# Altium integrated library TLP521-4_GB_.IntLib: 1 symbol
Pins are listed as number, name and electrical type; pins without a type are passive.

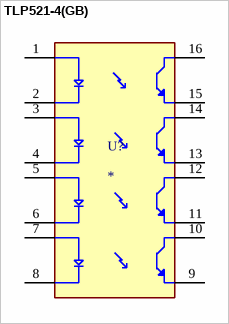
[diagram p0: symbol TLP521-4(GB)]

## TLP521-4(GB)
designator U?
Optocoupler, Quad, Transistor o/p; MF: Toshiba; MP: TLP521-4(GB)
footprint DIP762W50P254L2007H485Q16
pins: 1 A1, 2 C1, 3 A2, 4 C2, 5 A3, 6 C3, 7 A4, 8 C4, 9 ET4, 10 CT4, 11 ET3, 12 CT3, 13 ET2, 14 CT2, 15 ET1, 16 CT1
